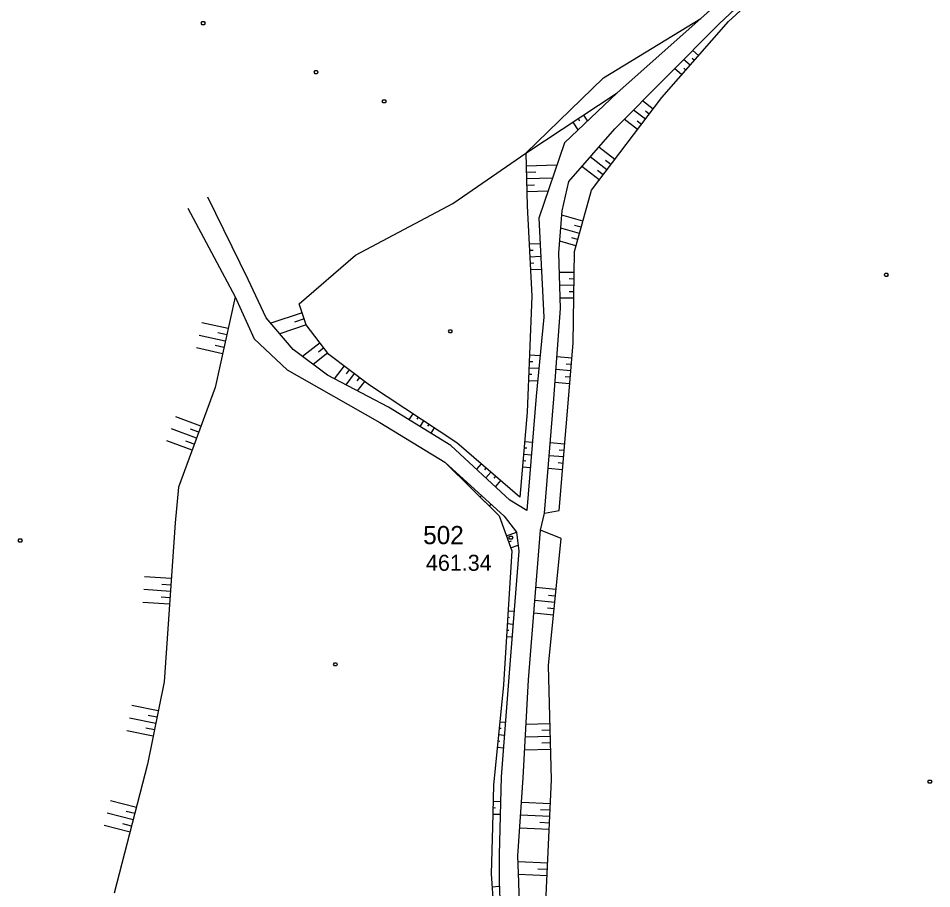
# Model space of a CAD drawing. Extents: x -664960 to -662754, y -993849 to -991145.
# Drawn here: x -664939.1 to -664768.4, y -993443.9 to -993281.2 of the extents above; entities that cross this region are included whole.
import ezdxf

# ---------------------------------------------------------------- set-up
doc = ezdxf.new("R2010")
doc.units = 0
for name, color, linetype in [('Vrstva 1', 7, 'Continuous'), ('Vrstva 13', 7, 'Continuous'), ('Vrstva 18', 7, 'Continuous'), ('Vrstva 27', 7, 'Continuous'), ('Vrstva 63', 7, 'Continuous'), ('Vrstva 8', 7, 'Continuous')]:
    doc.layers.add(name, color=color, linetype=linetype)

msp = doc.modelspace()

# ---------------------------------------------------------------- linework, layer by layer
at = {"layer": 'Vrstva 13'}
for points in [[(-664904.361, -993281.816), (-664904.181, -993282.116), (-664904.361, -993282.416), (-664904.721, -993282.416), (-664904.901, -993282.116), (-664904.721, -993281.816), (-664904.361, -993281.816)], [(-664870.535, -993296.43), (-664870.355, -993296.73), (-664870.535, -993297.03), (-664870.895, -993297.03), (-664871.075, -993296.73), (-664870.895, -993296.43), (-664870.535, -993296.43)], [(-664776.678, -993328.857), (-664776.498, -993329.157), (-664776.678, -993329.457), (-664777.038, -993329.457), (-664777.218, -993329.157), (-664777.038, -993328.857), (-664776.678, -993328.857)], [(-664858.174, -993339.417), (-664857.994, -993339.717), (-664858.174, -993340.017), (-664858.534, -993340.017), (-664858.714, -993339.717), (-664858.534, -993339.417), (-664858.174, -993339.417)], [(-664938.575, -993378.527), (-664938.395, -993378.827), (-664938.575, -993379.127), (-664938.935, -993379.127), (-664939.115, -993378.827), (-664938.935, -993378.527), (-664938.575, -993378.527)], [(-664879.654, -993401.675), (-664879.474, -993401.975), (-664879.654, -993402.275), (-664880.014, -993402.275), (-664880.194, -993401.975), (-664880.014, -993401.675), (-664879.654, -993401.675)], [(-664768.544, -993423.605), (-664768.364, -993423.905), (-664768.544, -993424.205), (-664768.904, -993424.205), (-664769.084, -993423.905), (-664768.904, -993423.605), (-664768.544, -993423.605)]]:
    msp.add_lwpolyline(points, dxfattribs=at)
at = {"layer": 'Vrstva 18'}
msp.add_lwpolyline([(-664883.27, -993290.95), (-664883.09, -993291.25), (-664883.27, -993291.55), (-664883.63, -993291.55), (-664883.81, -993291.25), (-664883.63, -993290.95), (-664883.27, -993290.95)], dxfattribs=at)
at = {"layer": 'Vrstva 27'}
for points in [[(-664804.41, -993274.79), (-664811.54, -993281.21), (-664827.16, -993295.12), (-664837.04, -993304.48), (-664841.78, -993318.55), (-664840.85, -993337.09), (-664842.28, -993351.83), (-664844.05, -993373.24), (-664847.2, -993371.25), (-664858.28, -993361.04), (-664869.93, -993353.88), (-664881.34, -993347.93), (-664887.72, -993343.1), (-664892.79, -993337.18), (-664896.15, -993330), (-664903.65, -993314.66)], [(-664845.56, -993442.68), (-664845.72, -993437.79), (-664844.75, -993423.16), (-664843.77, -993404.88), (-664841.52, -993376.89), (-664840.72, -993373.73), (-664839.02, -993352.33), (-664837.73, -993335.44), (-664838.07, -993325.04), (-664837.45, -993317.18), (-664836.19, -993311.7), (-664827.63, -993301.88), (-664808.09, -993282.21), (-664805.1, -993279.44)], [(-664907.4, -993316.68), (-664898.59, -993333.26), (-664895, -993341.14), (-664888.87, -993346.92), (-664871.52, -993356.74), (-664859.38, -993364.18), (-664848.27, -993374.26), (-664845.99, -993377.25), (-664845.52, -993380.79), (-664847.33, -993403.58), (-664848.82, -993423.01), (-664849.23, -993437.56), (-664849.24, -993442.58), (-664848.96, -993449.22)], [(-664830.71, -993567.69), (-664837.96, -993568.55), (-664845.98, -993568.5), (-664851.25, -993566.43), (-664854.46, -993563.69), (-664857.68, -993559.18), (-664861.44, -993545.16), (-664860.14, -993536.81), (-664858.11, -993534.64), (-664849.37, -993532.3), (-664832.51, -993531.15), (-664826.16, -993527.24), (-664823.02, -993524.47), (-664819.37, -993519.36), (-664818.69, -993514.28), (-664818.39, -993509.72), (-664830.53, -993488.08), (-664838.71, -993474.83), (-664843.26, -993463.66), (-664845.33, -993449.14), (-664845.56, -993442.68)]]:
    msp.add_lwpolyline(points, dxfattribs=at)
at = {"layer": 'Vrstva 63'}
for p, q in [((-664811.938, -993288.164), (-664813.045, -993287.198)), ((-664813.515, -993289.972), (-664814.74, -993288.904)), ((-664812.726, -993289.068), (-664813.115, -993288.729)), ((-664815.093, -993291.781), (-664816.435, -993290.61)), ((-664814.304, -993290.876), (-664814.731, -993290.504)), ((-664844.26, -993306.4), (-664827.16, -993295.12)), ((-664820.435, -993298.176), (-664822.436, -993296.652)), ((-664833.471, -993299.283), (-664832.734, -993300.4)), ((-664821.89, -993300.085), (-664824.142, -993298.369)), ((-664821.163, -993299.131), (-664821.871, -993298.591)), ((-664835.474, -993300.604), (-664834.503, -993302.076)), ((-664834.472, -993299.944), (-664834.188, -993300.375)), ((-664823.345, -993301.994), (-664825.848, -993300.086)), ((-664822.617, -993301.04), (-664823.409, -993300.436)), ((-664827.615, -993307.598), (-664830.619, -993305.309)), ((-664829.07, -993309.507), (-664832.2, -993307.122)), ((-664828.342, -993308.553), (-664829.364, -993307.775)), ((-664844.193, -993308.77), (-664838.43, -993308.606)), ((-664830.524, -993311.416), (-664833.78, -993308.935)), ((-664829.797, -993310.462), (-664830.86, -993309.652)), ((-664844.158, -993309.969), (-664842.387, -993309.919)), ((-664844.124, -993311.169), (-664839.247, -993311.03)), ((-664844.09, -993312.368), (-664842.613, -993312.326)), ((-664844.056, -993313.568), (-664840.063, -993313.454)), ((-664833.591, -993319.1), (-664837.515, -993318.009)), ((-664833.913, -993320.256), (-664835.144, -993319.914)), ((-664834.234, -993321.412), (-664837.708, -993320.447)), ((-664843.621, -993323.378), (-664841.543, -993323.273)), ((-664834.877, -993323.725), (-664837.9, -993322.884)), ((-664834.555, -993322.569), (-664835.637, -993322.268)), ((-664843.561, -993324.576), (-664842.869, -993324.541)), ((-664843.501, -993325.775), (-664841.423, -993325.67)), ((-664843.44, -993326.973), (-664842.749, -993326.938)), ((-664843.38, -993328.172), (-664841.303, -993328.067)), ((-664835.228, -993328.748), (-664837.95, -993328.708)), ((-664835.245, -993329.948), (-664836.133, -993329.935)), ((-664835.263, -993331.147), (-664837.872, -993331.109)), ((-664835.298, -993333.547), (-664837.793, -993333.511)), ((-664835.28, -993332.347), (-664836.13, -993332.335)), ((-664886.056, -993336.245), (-664891.904, -993338.215)), ((-664899.896, -993339.207), (-664904.78, -993338.134)), ((-664885.29, -993338.52), (-664890.221, -993340.18)), ((-664885.673, -993337.383), (-664887.468, -993337.987)), ((-664900.411, -993341.551), (-664905.294, -993340.479)), ((-664900.153, -993340.379), (-664901.78, -993340.022)), ((-664882.713, -993341.868), (-664886.002, -993344.4)), ((-664900.925, -993343.895), (-664905.809, -993342.823)), ((-664900.668, -993342.723), (-664902.294, -993342.366)), ((-664881.249, -993343.769), (-664884.019, -993345.902)), ((-664881.981, -993342.818), (-664882.99, -993343.595)), ((-664843.597, -993345.328), (-664842.951, -993345.353)), ((-664843.551, -993344.129), (-664841.54, -993344.206)), ((-664835.65, -993344.72), (-664838.421, -993344.491)), ((-664878.222, -993346.171), (-664880.057, -993348.599)), ((-664877.265, -993346.895), (-664877.835, -993347.65)), ((-664843.643, -993346.527), (-664841.773, -993346.599)), ((-664835.848, -993347.112), (-664838.604, -993346.884)), ((-664835.749, -993345.916), (-664836.669, -993345.84)), ((-664876.307, -993347.619), (-664877.899, -993349.724)), ((-664875.35, -993348.343), (-664875.84, -993348.99)), ((-664843.735, -993348.926), (-664842.005, -993348.992)), ((-664843.689, -993347.727), (-664843.089, -993347.75)), ((-664835.947, -993348.308), (-664836.862, -993348.232)), ((-664874.393, -993349.067), (-664875.741, -993350.849)), ((-664836.046, -993349.504), (-664838.787, -993349.277)), ((-664904.972, -993357.436), (-664909.665, -993355.71)), ((-664865.369, -993355.121), (-664866.103, -993356.232)), ((-664864.368, -993355.783), (-664864.605, -993356.142)), ((-664863.366, -993356.445), (-664864.057, -993357.489)), ((-664862.365, -993357.106), (-664862.588, -993357.443)), ((-664905.801, -993359.688), (-664910.493, -993357.962)), ((-664905.386, -993358.562), (-664906.949, -993357.987)), ((-664861.364, -993357.768), (-664862.011, -993358.747)), ((-664906.629, -993361.941), (-664911.322, -993360.215)), ((-664906.215, -993360.815), (-664907.778, -993360.24)), ((-664844.431, -993360.286), (-664842.989, -993360.41)), ((-664836.982, -993360.815), (-664839.676, -993360.592)), ((-664844.636, -993362.677), (-664843.187, -993362.801)), ((-664844.533, -993361.481), (-664844.052, -993361.523)), ((-664837.081, -993362.011), (-664837.977, -993361.937)), ((-664844.739, -993363.872), (-664844.255, -993363.914)), ((-664837.18, -993363.207), (-664839.866, -993362.984)), ((-664837.279, -993364.403), (-664838.172, -993364.329)), ((-664852.602, -993364.472), (-664853.467, -993365.475)), ((-664851.693, -993365.256), (-664851.99, -993365.6)), ((-664850.785, -993366.04), (-664851.702, -993367.102)), ((-664844.842, -993365.068), (-664843.385, -993365.193)), ((-664837.378, -993365.599), (-664840.056, -993365.377)), ((-664849.877, -993366.825), (-664850.19, -993367.188)), ((-664848.968, -993367.609), (-664849.936, -993368.729)), ((-664852.786, -993370.683), (-664852.515, -993370.408)), ((-664851.932, -993371.525), (-664851.83, -993371.422)), ((-664851.078, -993372.368), (-664850.737, -993372.022)), ((-664847.882, -993377.926), (-664845.99, -993377.25)), ((-664847.478, -993379.056), (-664846.929, -993378.86)), ((-664847.074, -993380.186), (-664845.667, -993379.683)), ((-664910.507, -993385.95), (-664915.494, -993385.598)), ((-664910.676, -993388.344), (-664915.664, -993387.992)), ((-664910.591, -993387.147), (-664912.252, -993387.03)), ((-664838.606, -993388.012), (-664842.384, -993387.632)), ((-664910.761, -993389.541), (-664912.422, -993389.424)), ((-664838.846, -993390.4), (-664842.576, -993390.025)), ((-664838.726, -993389.206), (-664839.976, -993389.08)), ((-664910.845, -993390.738), (-664915.833, -993390.386)), ((-664838.966, -993391.594), (-664840.2, -993391.47)), ((-664847.644, -993393.168), (-664847.266, -993393.191)), ((-664847.571, -993391.97), (-664846.414, -993392.042)), ((-664839.087, -993392.788), (-664842.768, -993392.418)), ((-664847.718, -993394.366), (-664846.604, -993394.434)), ((-664847.865, -993396.761), (-664846.794, -993396.827)), ((-664847.792, -993395.564), (-664847.428, -993395.586)), ((-664912.954, -993410.67), (-664917.857, -993409.694)), ((-664913.423, -993413.024), (-664918.326, -993412.047)), ((-664913.188, -993411.847), (-664914.821, -993411.522)), ((-664913.657, -993414.201), (-664915.29, -993413.876)), ((-664849.218, -993413.887), (-664848.856, -993413.922)), ((-664849.101, -993412.692), (-664848.037, -993412.797)), ((-664839.725, -993413.071), (-664844.216, -993413.197)), ((-664913.892, -993415.378), (-664918.795, -993414.401)), ((-664849.336, -993415.081), (-664848.22, -993415.191)), ((-664839.657, -993415.47), (-664844.345, -993415.602)), ((-664839.691, -993414.271), (-664841.219, -993414.314)), ((-664849.454, -993416.275), (-664849.074, -993416.313)), ((-664839.624, -993416.67), (-664841.217, -993416.715)), ((-664849.572, -993417.469), (-664848.404, -993417.584)), ((-664839.59, -993417.869), (-664844.474, -993418.006)), ((-664917.027, -993428.721), (-664921.868, -993427.47)), ((-664850.347, -993427.559), (-664848.949, -993427.595)), ((-664850.378, -993428.759), (-664849.913, -993428.77)), ((-664839.637, -993428.045), (-664845.057, -993427.793)), ((-664839.693, -993429.244), (-664841.506, -993429.16)), ((-664917.628, -993431.045), (-664922.469, -993429.794)), ((-664917.327, -993429.883), (-664918.94, -993429.466)), ((-664850.409, -993429.958), (-664849.017, -993429.994)), ((-664839.749, -993430.443), (-664845.216, -993430.189)), ((-664918.228, -993433.368), (-664923.069, -993432.118)), ((-664917.928, -993432.206), (-664919.54, -993431.79)), ((-664839.86, -993432.84), (-664845.375, -993432.584)), ((-664839.804, -993431.641), (-664841.633, -993431.556)), ((-664840.152, -993439.122), (-664845.685, -993438.865)), ((-664840.208, -993440.321), (-664842.018, -993440.237)), ((-664840.263, -993441.52), (-664845.606, -993441.271)), ((-664850.552, -993443.541), (-664849.203, -993443.452))]:
    msp.add_line(p, q, dxfattribs=at)
for points in [[(-664840.72, -993373.73), (-664838.01, -993373.23), (-664835.42, -993341.94), (-664835.17, -993324.78), (-664831.99, -993313.34), (-664818.8, -993296.03), (-664806.36, -993281.77), (-664791.35, -993268), (-664775.38, -993254.53)], [(-664844.26, -993306.4), (-664829.72, -993292.3), (-664811.54, -993281.21)], [(-664845.33, -993370.75), (-664857.11, -993360.58), (-664873.45, -993349.78), (-664881.04, -993344.04), (-664885.29, -993338.52), (-664886.62, -993334.57), (-664876.05, -993325.51), (-664857.91, -993315.8), (-664844.26, -993306.4), (-664843.98, -993316.24), (-664843.13, -993333.15), (-664843.96, -993354.81), (-664845.33, -993370.75)], [(-664898.59, -993333.26), (-664902.31, -993350.2), (-664909.16, -993368.82), (-664909.77, -993375.53), (-664911.87, -993405.23), (-664914.94, -993420.64), (-664921.16, -993444.72)], [(-664859.38, -993364.18), (-664849.21, -993374.21), (-664846.88, -993380.73), (-664848.42, -993405.79), (-664850.27, -993424.55), (-664850.47, -993432.34), (-664850.71, -993441.15), (-664850.29, -993447.5), (-664844.71, -993471.29), (-664834.5, -993490.33), (-664830.27, -993499.01), (-664825.23, -993511.72), (-664825.56, -993515.57), (-664828.92, -993520.73), (-664837.93, -993524.99), (-664849.55, -993525.38), (-664857.49, -993525.44), (-664862.48, -993529.15), (-664867.68, -993537.12)], [(-664819.37, -993519.36), (-664812.5, -993519.97), (-664812.63, -993519.54), (-664811.67, -993514.99), (-664812.72, -993505.47), (-664816.89, -993495.87), (-664823.65, -993483.27), (-664835.78, -993463.54), (-664840.62, -993449.19), (-664839.43, -993423.59), (-664840.03, -993402.16), (-664837.64, -993378.42), (-664841.52, -993376.89)]]:
    msp.add_lwpolyline(points, dxfattribs=at)
at = {"layer": 'Vrstva 8'}
msp.add_lwpolyline([(-664846.86, -993377.99), (-664846.68, -993378.29), (-664846.86, -993378.59), (-664847.22, -993378.59), (-664847.4, -993378.29), (-664847.22, -993377.99), (-664846.86, -993377.99)], dxfattribs=at)

# ---------------------------------------------------------------- texts
at = {"layer": 'Vrstva 1'}
msp.add_text('502', height=3.4, dxfattribs=at).set_placement((-664863.424, -993379.508))
at = {"layer": 'Vrstva 63'}
msp.add_text('461.34', height=3, dxfattribs=at).set_placement((-664862.9, -993384.488))

doc.saveas('drawing.dxf')
